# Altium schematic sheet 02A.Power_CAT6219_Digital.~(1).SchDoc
size A4; CompanyName: 广州周立功单片机科技有限公司; DocumentNumber: 2; SheetNumber: 2; SheetTotal: 7; PageSetup: Record=PageOptions¦CenterHorizontal=True¦CenterVertical=True¦PrintScale=1.00¦XCorrection=1.00¦YCorrection=1.00¦PrintKind=0¦BorderSize=5000000¦LeftOffset=0¦BottomOffset=0¦Orientation=2¦PaperLength=1000¦PaperWidth=1000¦Scale=100¦PaperSource=7¦PrintQuality=600¦MediaType=1¦DitherType=10¦PaperKind=A4¦PrintScaleMode=1; DesignDate: 20170717; CheckDate: 20170717; SheetName: POWER_CAT6219; SheetVersion: V1.00; SheetDescription: 基于CAT6219的数字电源电路
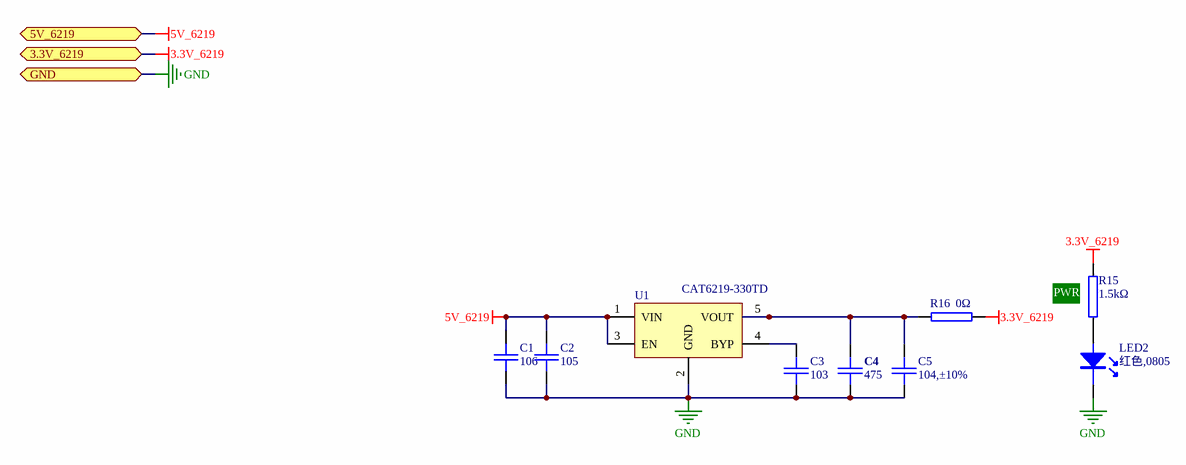
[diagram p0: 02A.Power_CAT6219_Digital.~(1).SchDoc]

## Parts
C1  106  [0805C]
C2  105  [0603C]
C3  103  [0603C]
C4  475  [0805C]
C5  104,±10%  [0603C]
LED2  value 红色,0805  [LED-0805]  (hidden comment: LED1)
R15  1.5kΩ  [0603R]
R16  0Ω  [0603R]
U1  CAT6219-330TD  [SOT-23-5]

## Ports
3.3V_6219, 5V_6219, GND

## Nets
3.3V_6219: R15.1 R16.2 ; port 3.3V_6219
5V_6219: C1.1 C2.1 U1.1(VIN) U1.3(EN) ; port 5V_6219
GND: C1.2 C2.2 C3.2 C4.2 C5.2 LED2.2 U1.2(GND) ; port GND
NetC3_1: C3.1 U1.4(BYP)
NetC4_1: C4.1 C5.1 R16.1 U1.5(VOUT)
NetLED2_1: LED2.1 R15.2

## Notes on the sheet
- (near R15) PWR

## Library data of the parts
C1 = 1.02.02.0055: 106,10μF,±10%,10V,X5R,0805,RoHS; 名称: 电容; 封装: 0805; 贴片和直插: SMT; 器件优选方案: 量产物料,优先选用; 设备封装名称: C0805_106_X5R_10V_10%
C2 = 1.02.01.0036: 105,1μF,±10%,16V,X7R,0603,*,RoHS; 名称: 电容; 封装: 0603; 设备封装名称: C0603_105_X7R_16V_10%; 厂商: TDK; 贴片和直插: SMT; 器件优选方案: 量产物料,不推荐使用
C3 = 1.02.01.0024: 103,±10%,50V,X7R,0603,*,RoHS; 名称: 电容; 封装: 0603; 设备封装名称: C0603_103_X7R_50V_10%; 厂商: muRata; 贴片和直插: SMT; 器件优选方案: 量产物料,不推荐使用
C4 = 1.02.02.0064: 475,±10%,16V,X7R,0805,RoHS; 名称: 电容; 封装: 0805; 设备封装名称: C0805_475_X7R_16V_10%; 贴片和直插: SMT; 器件优选方案: 优先选用
C5 = 1.02.01.0032: Capacitor; 名称: 电容; 封装: 0603; 设备封装名称: C0603_104_X7R_50V_10%; 厂商: muRata; 型号: 104,±10%,50V,X7R; 贴片和直插: SMT; 器件优选方案: 量产物料,优先选用
LED2 = 1.04.05.0001: 红色,0805,0805,RoHS; 名称: 发光二极管; 封装: 0805; 设备封装名称: LED0805-RED; 贴片和直插: SMT; 器件优选方案: 样品物料,谨慎选用
R15 = 1.01.01.0037: 1.5KΩ,0603,*,RoHS; 名称: 电阻; 封装: 0603; 设备封装名称: R0603_1.5K; 厂商: Ralec; 贴片和直插: SMT; 器件优选方案: 状态正常
R16 = 1.01.01.0001: 名称: 电阻; 封装: 0603; 设备封装名称: R0603_0R; 厂商: Ralec; 贴片和直插: SMT; 器件优选方案: 状态正常
U1 = 1.05.10.0321: CAT6219-330TD,TSOT-23-5,ON,RoHS; 名称: 集成电路; 设备封装名称: TSOT-23-5_CAT6219-330TD-GT3; 贴片和直插: SMT; 器件优选方案: 量产物料,优先选用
